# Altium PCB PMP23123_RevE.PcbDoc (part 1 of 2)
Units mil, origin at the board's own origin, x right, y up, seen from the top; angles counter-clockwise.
Board outline 4000 x 3800 mil, 4 copper layers (Top Layer, Layer 1, Layer 2, Bottom Layer), stack 76 mil thick; 128 components, 55 nets, 360 pads, 207 vias.
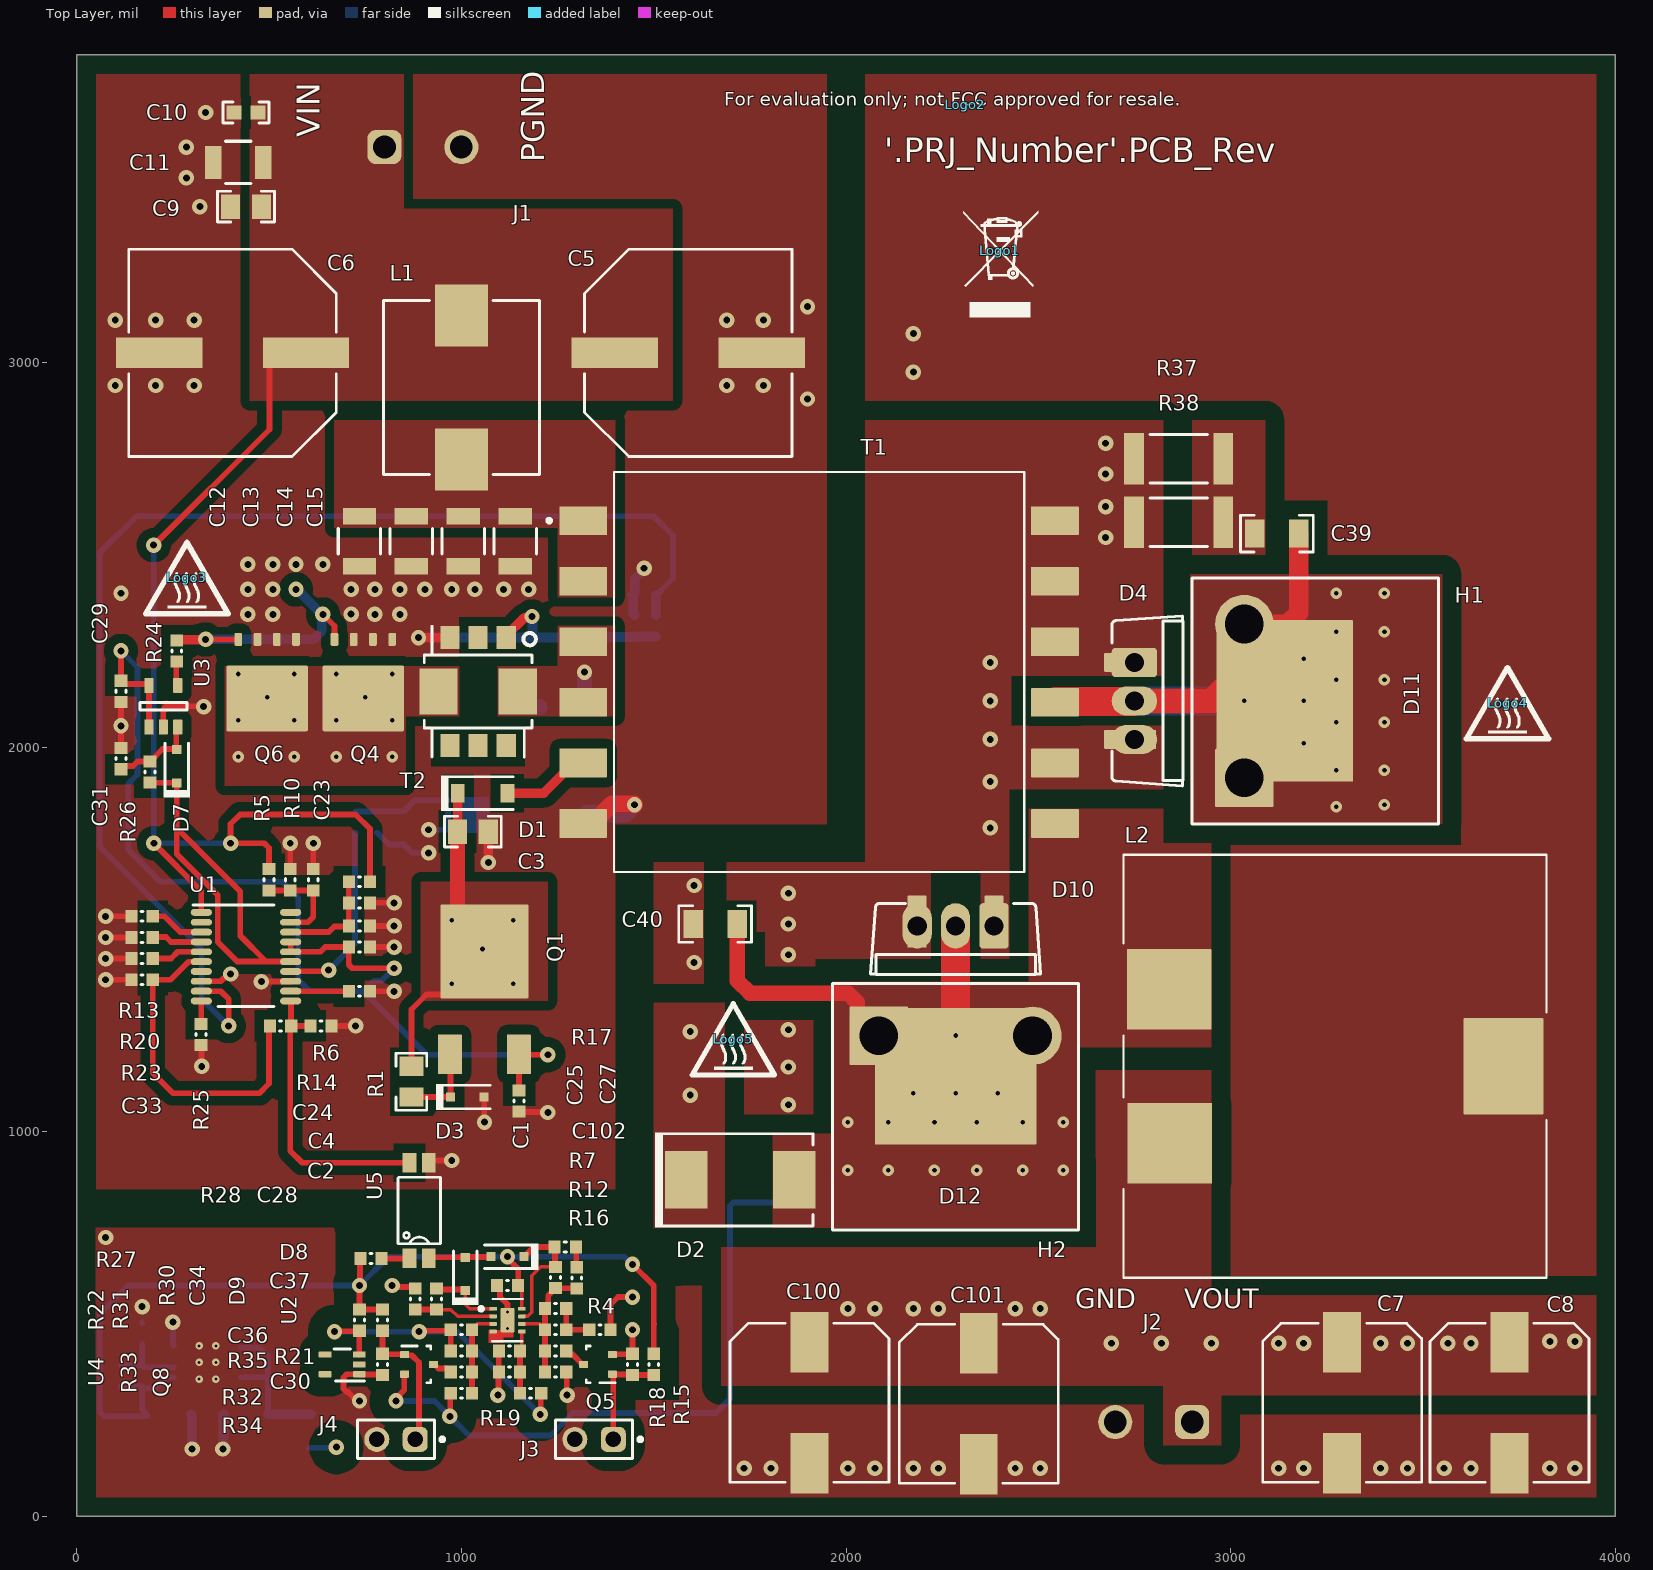
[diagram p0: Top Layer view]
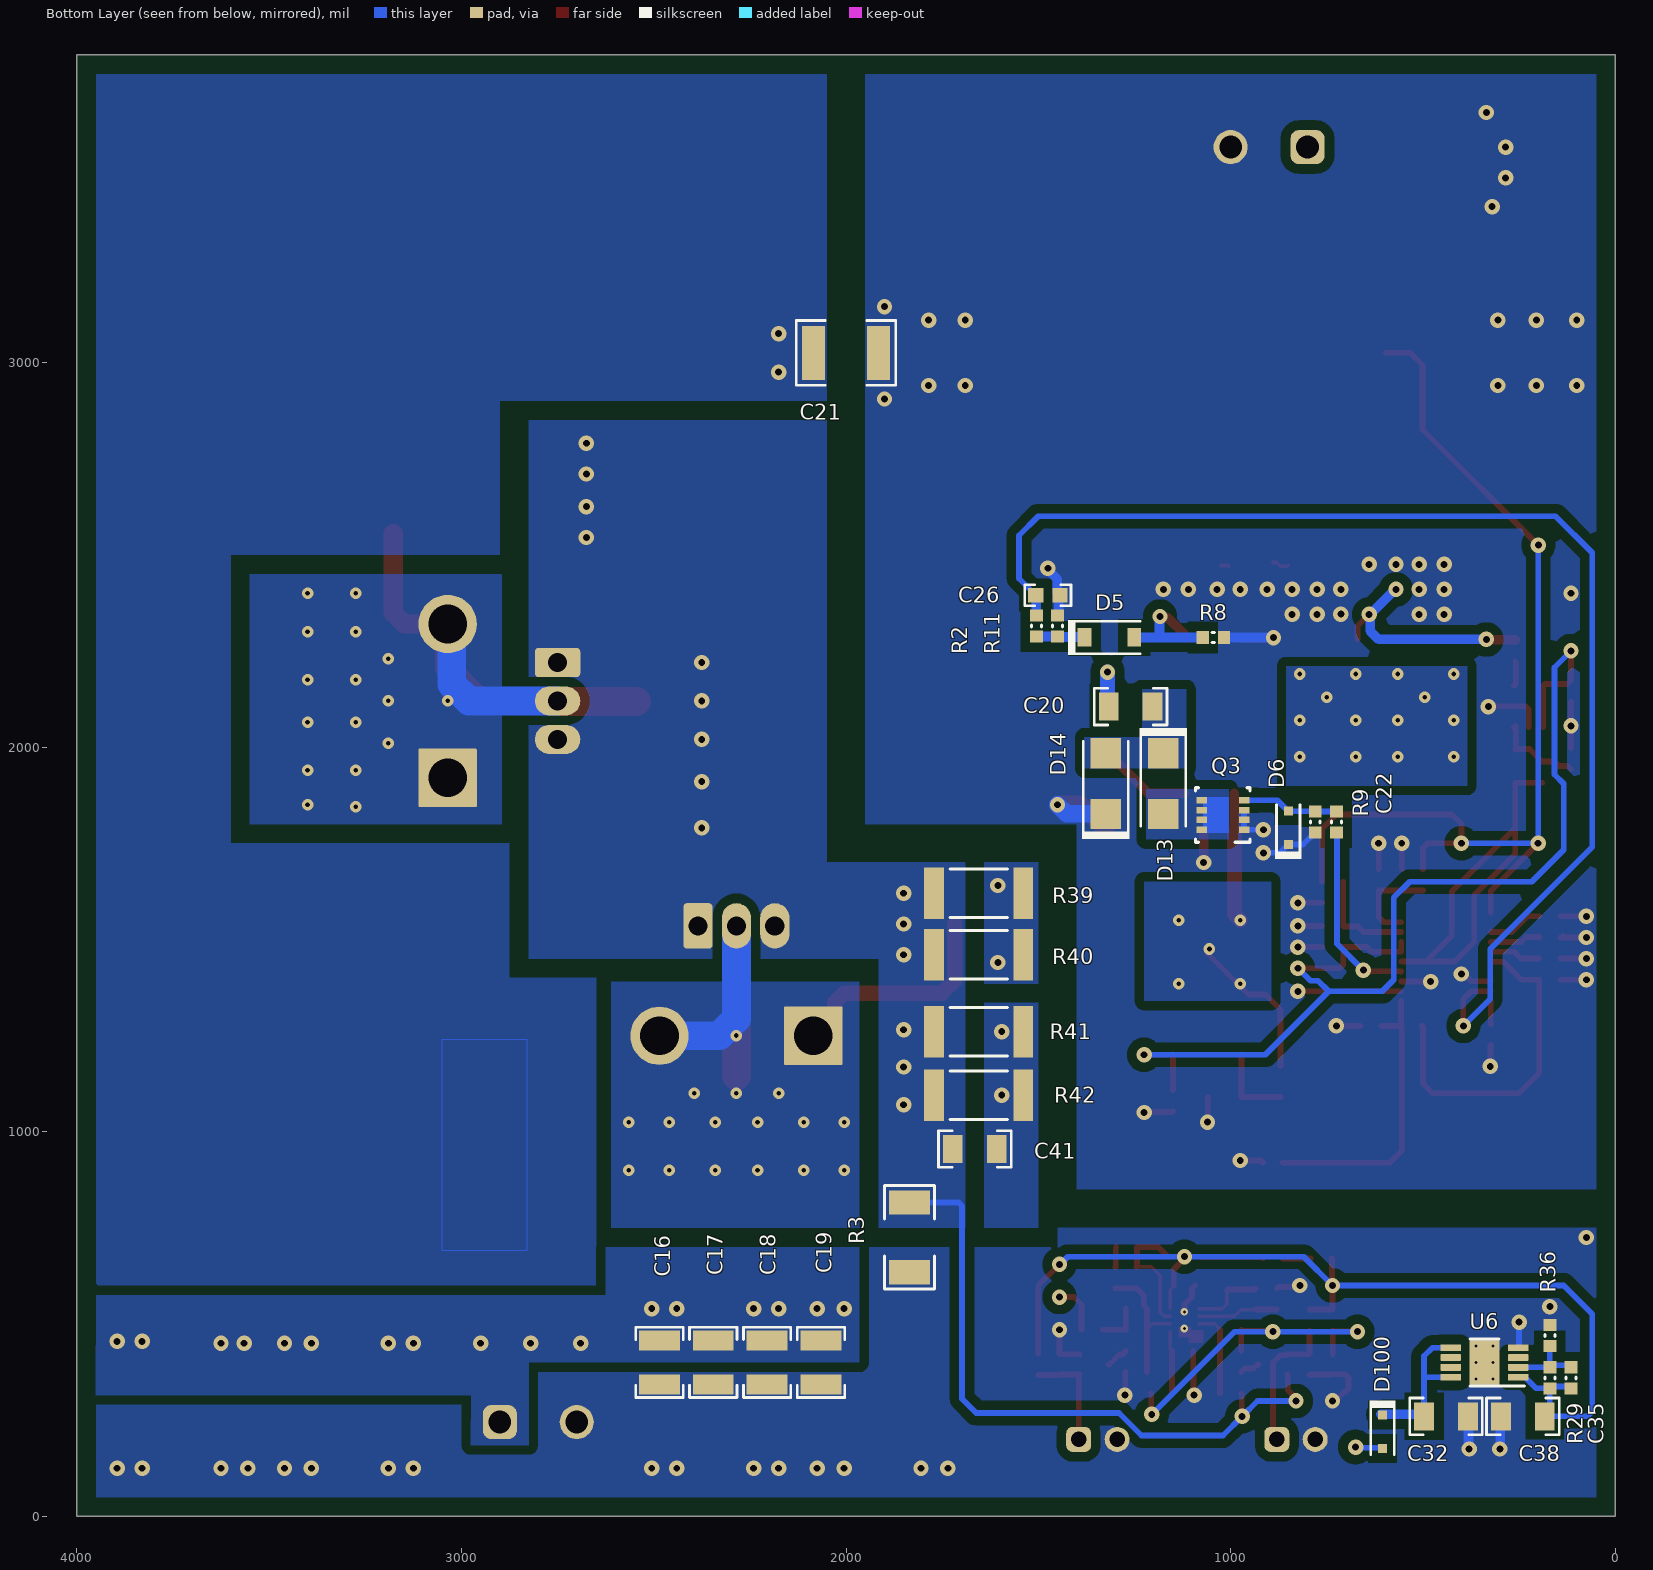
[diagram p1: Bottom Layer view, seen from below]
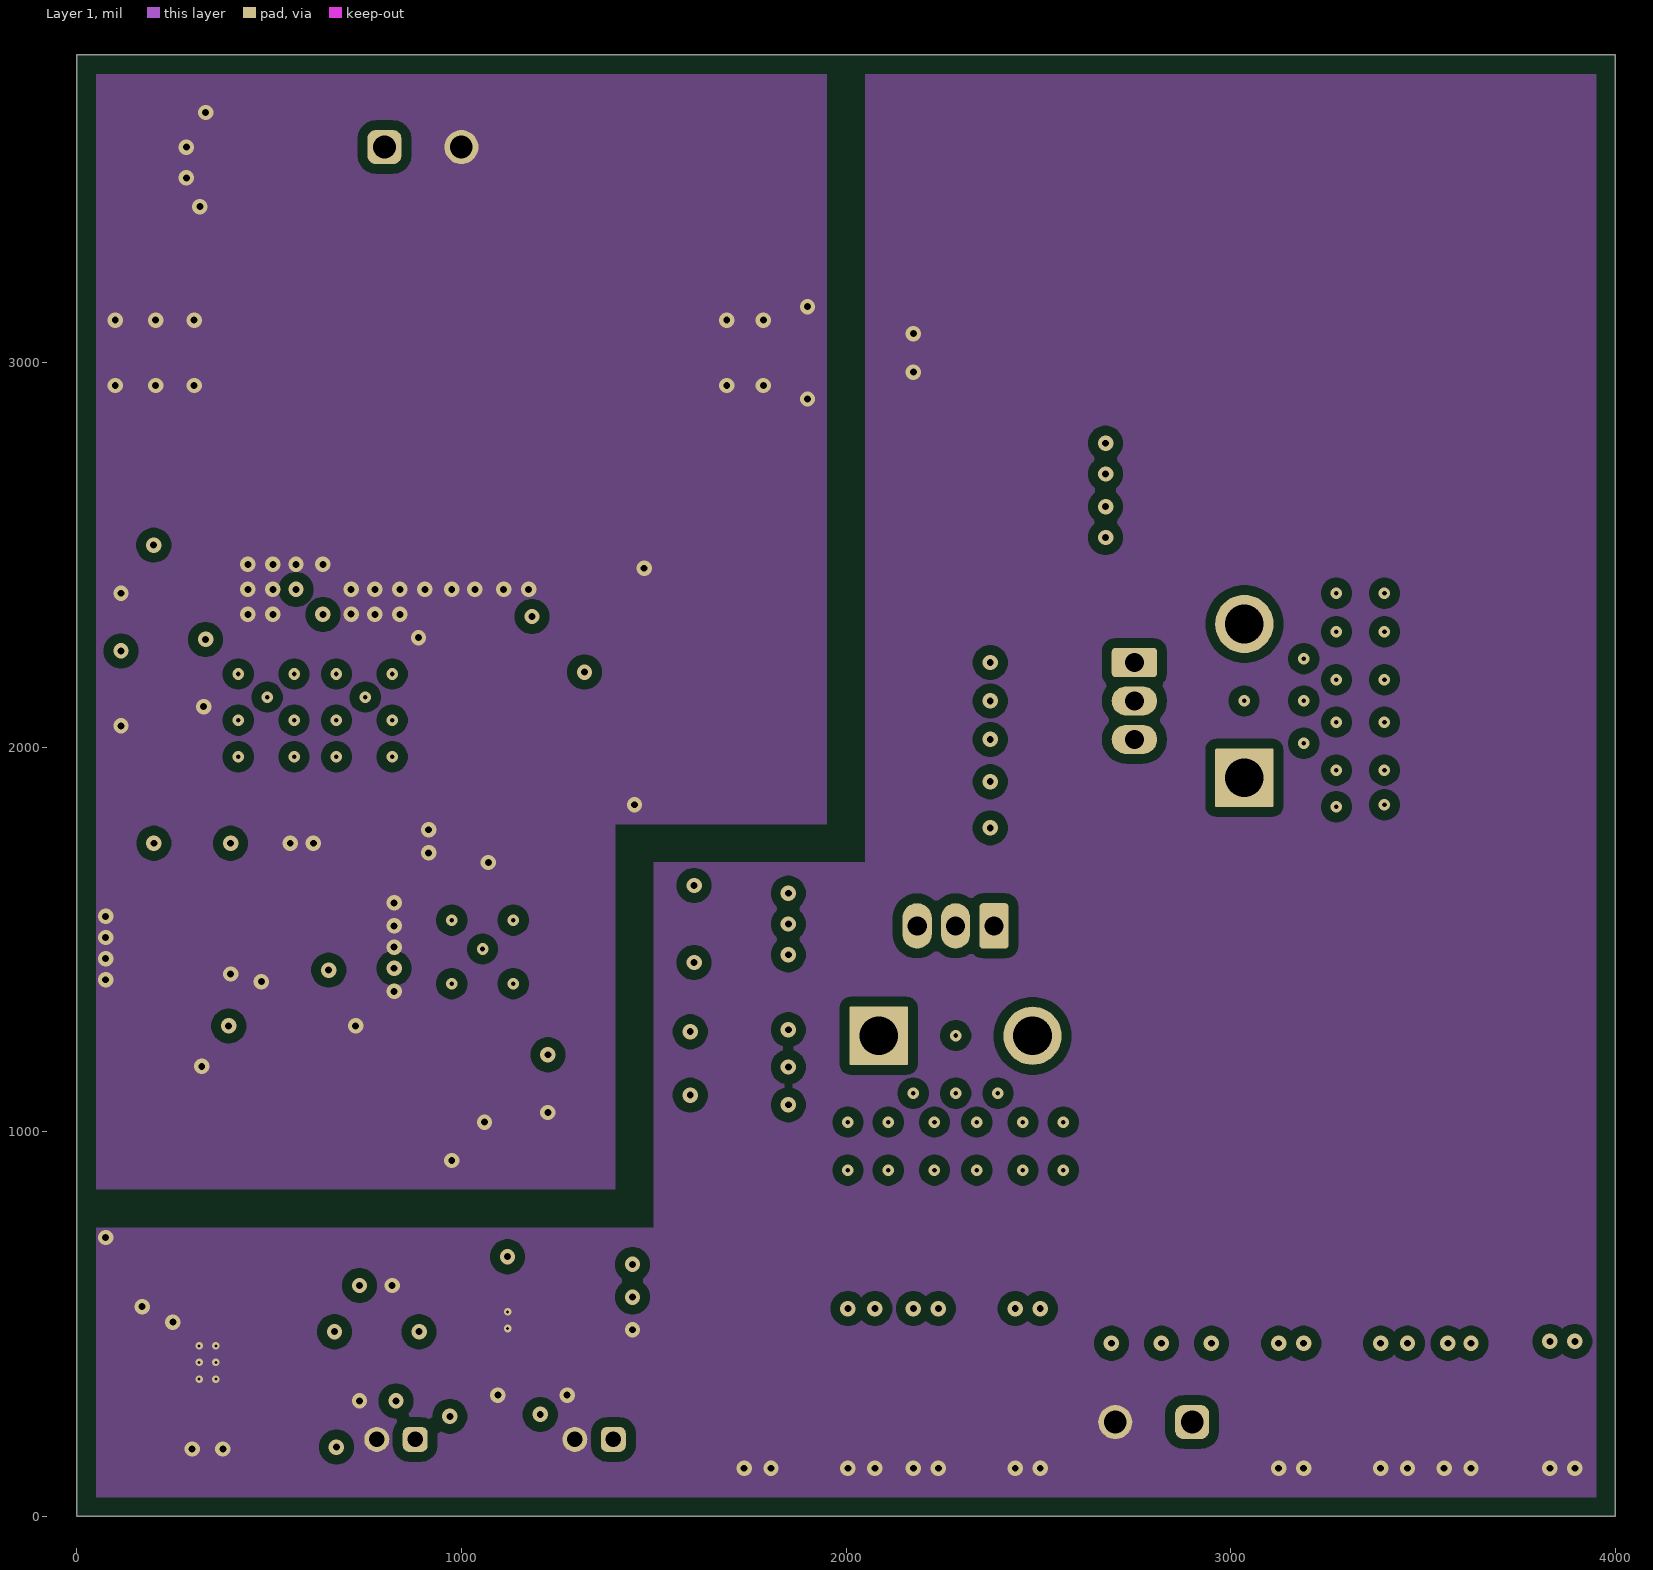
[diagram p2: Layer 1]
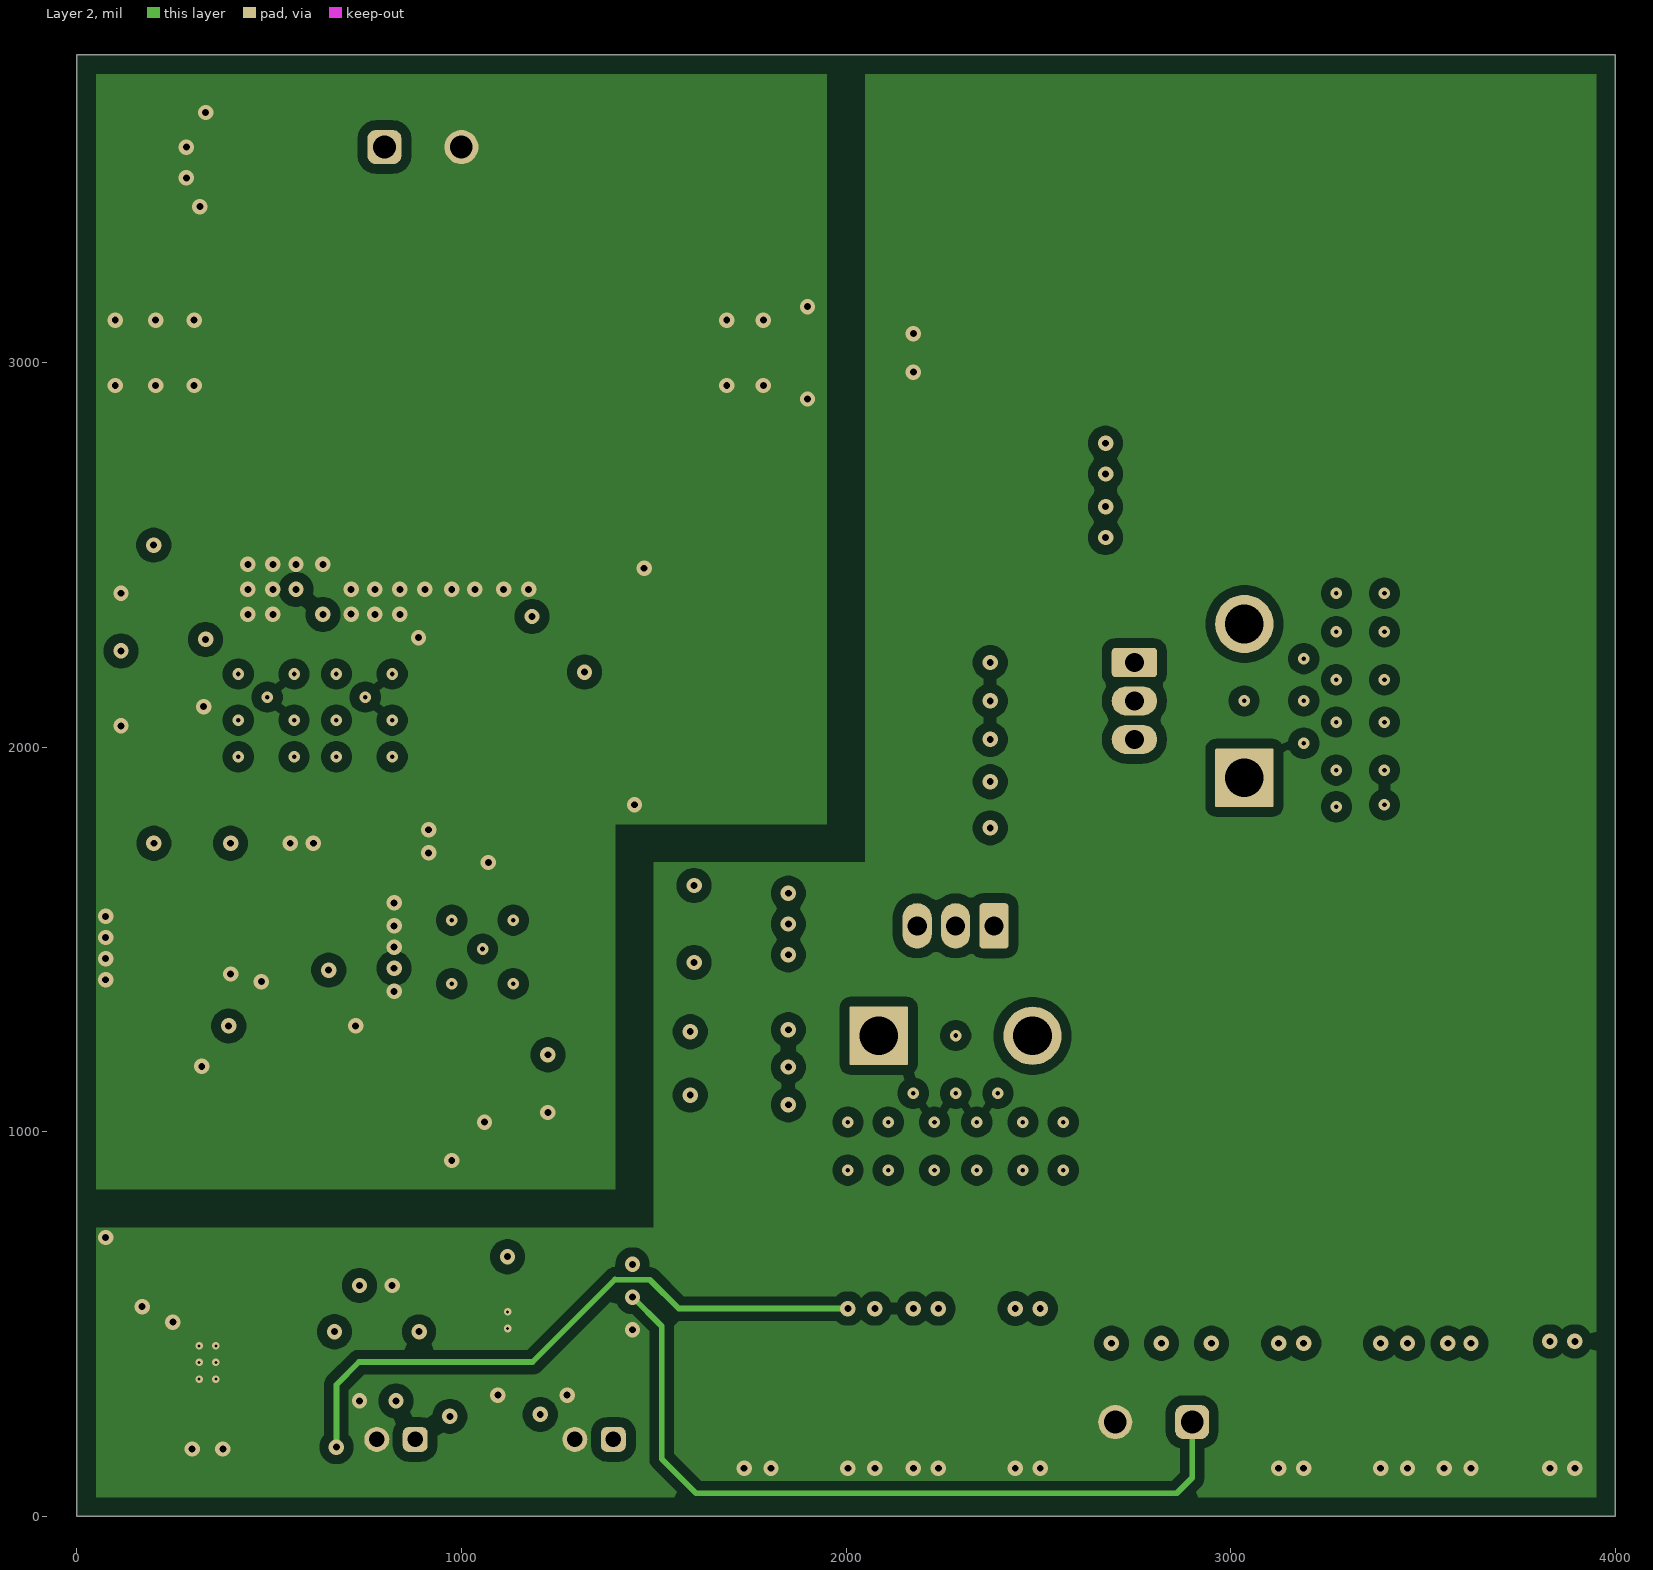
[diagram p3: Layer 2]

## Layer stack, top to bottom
Top Solder: solder mask 0.4, Solder Resist, Dk 3.5
Top Layer: signal copper 2.8
Dielectric 1: prepreg 2.8, PP-006, Dk 4.1
Layer 1: signal copper 2.8
Dielectric1: core 59.2, FR-4 High Tg, Dk 4.8
Layer 2: signal copper 2.8
Dielectric 2: prepreg 2.8, PP-006, Dk 4.1
Bottom Layer: signal copper 2.8
Bottom Solder: solder mask 0.4, Solder Resist, Dk 3.5

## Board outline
0,0 0,3800 4000,3800 4000,0

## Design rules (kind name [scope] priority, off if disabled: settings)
AcuteAngle [All] p1: minimum=4.50000000000000E+0001 checktracksonly=FALSE
AssemblyTestPointUsage [All] p1: valid=2
BoardOutlineClearance BoardOutlineClearance_MountingHoles [OnCopper and InComponentClass('Mounting Holes')] p1: gap=39.37 ignorepadtopadclearanceinfootprint=FALSE
BoardOutlineClearance BoardOutlineClearance_Poly [OnCopper and IsPoly] p2: gap=25 ignorepadtopadclearanceinfootprint=FALSE
BoardOutlineClearance [OnCopper and Not InComponentClass('Logo') and not InComponentClass('FiducialMark') and not InRegion(1000,500,4000,800) and not InPoly] p3: gap=40 ignorepadtopadclearanceinfootprint=FALSE
Clearance Clearance_1 [InNamedPolygon('TOP_LAYER_GND_P051')] p1: gap=50 ignorepadtopadclearanceinfootprint=FALSE
Clearance Clearance_Keepouts [((IsTrack Or IsArc) And Not InPoly) And IsFree and IsKeepOut vs ((IsTrack Or IsArc) And Not InPoly) And IsFree and IsKeepOut] p2: gap=0 ignorepadtopadclearanceinfootprint=FALSE
Clearance Clearance_Poly [InPolygon] p3: gap=25 ignorepadtopadclearanceinfootprint=TRUE
Clearance Clearance_FiducialMark [IsKeepOut and InComponentClass('FiducialMark') vs IsPad and InComponentClass('FiducialMark')] p4: gap=0 ignorepadtopadclearanceinfootprint=FALSE
Clearance [All] p5: gap=7.87 ignorepadtopadclearanceinfootprint=TRUE
ComponentClearance ComponentClearance_4 [InComponent('D12') vs InComponent('H2')] p1: gap=0 collisioncheckmode=3 verticalgap=0 showdistances=FALSE
ComponentClearance ComponentClearance_3 [InComponent('D12') vs InComponent('D10')] p2: gap=0 collisioncheckmode=3 verticalgap=0 showdistances=FALSE
ComponentClearance ComponentClearance_2 [InComponent('D11') vs InComponent('H1')] p3: gap=0 collisioncheckmode=3 verticalgap=0 showdistances=FALSE
ComponentClearance ComponentClearance_1 [InComponent('D11') vs InComponent('D4')] p4: gap=0 collisioncheckmode=3 verticalgap=0 showdistances=FALSE
ComponentClearance ComponentClearance_MountingHoles_FiducialMarks [InComponentClass('Mounting Holes') vs InComponentClass('FiducialMark')] p5: gap=50 collisioncheckmode=3 verticalgap=10 showdistances=FALSE
ComponentClearance ComponentClearance_Shunt [InComponentClass('Header') vs InComponentClass('Shunt')] p6: gap=0 collisioncheckmode=3 verticalgap=0 showdistances=FALSE
ComponentClearance ComponentClearance_Logo [InComponentClass('Logo')] p7: gap=30 collisioncheckmode=3 verticalgap=10 showdistances=FALSE
ComponentClearance ComponentClearance_ScrewToNut [(HasFootprint('NY PMS 440 0025 PH')) vs (HasFootprint('Keystone_1902C'))] p8: gap=5 collisioncheckmode=3 verticalgap=10 showdistances=FALSE
ComponentClearance ComponentClearance_MountingHoles [InComponentClass('Mounting Holes')] p9: gap=100 collisioncheckmode=3 verticalgap=100000 showdistances=FALSE
ComponentClearance ComponentClearance_SmallPassives [HasFootprint('0201*') or HasFootprint('0402*') or HasFootprint('0508') or HasFootprint('0603*') or HasFootprint('0612') or HasFootprint('0805*') or HasFootprint('0815*') or HasFootprint('0830*') or HasFootprint('1206*') or HasFootprint('1210*') or HasFootprint('1808*') or HasFootprint('1812*') or HasFootprint('1825*') or HasFootprint('2010*') or HasFootprint('2220*') or HasFootprint('2225*') or HasFootprint('2512*') or HasFootprint('2728*') or HasFootprint('3518*') vs HasFootprint('0201*') or HasFootprint('0402*') or HasFootprint('0508') or HasFootprint('0603*') or HasFootprint('0612') or HasFootprint('0805*') or HasFootprint('0815*') or HasFootprint('0830*') or HasFootprint('1206*') or HasFootprint('1210*') or HasFootprint('1808*') or HasFootprint('1812*') or HasFootprint('1825*') or HasFootprint('2010*') or HasFootprint('2220*') or HasFootprint('2225*') or HasFootprint('2512*') or HasFootprint('2728*') or HasFootprint('3518*')] p10: gap=14.96 collisioncheckmode=3 verticalgap=10 showdistances=FALSE
ComponentClearance ComponentClearance_THtoSMT [IsThruComponent vs IsSMTComponent] p11: gap=30 collisioncheckmode=3 verticalgap=30 showdistances=FALSE
ComponentClearance ComponentClearance_THtoTH [IsThruComponent vs IsThruComponent] p12: gap=20 collisioncheckmode=3 verticalgap=30 showdistances=FALSE
ComponentClearance [All] p13: gap=20 collisioncheckmode=3 verticalgap=10 showdistances=FALSE
DiffPairsRouting [All] p1: maxlimit=100 minlimit=10 mostfreqgap=10 toplayer_minwidth=15 toplayer_maxwidth=15 toplayer_prefwidth=15 midlayer1_minwidth=15 midlayer1_maxwidth=15 midlayer1_prefwidth=15 midlayer2_minwidth=15 midlayer2_maxwidth=15 midlayer2_prefwidth=15 bottomlayer_minwidth=15 bottomlayer_maxwidth=15 bottomlayer_prefwidth=15 maxuncoupledlength=1000
FabricationTestPointUsage TestPointUsage [All] p1: valid=2 allowmultiple=FALSE
FabricationTestpoint Testpoint [All] p1: side=3 testpointundercomponent=TRUE minsize=40 maxsize=100 preferedsize=60 minholesize=0 maxholesize=40 preferedholesize=32 testpointgrid=1 allowsidetop=TRUE allowsidebottom=TRUE usegrid=TRUE gridtolerance=0.01
FanoutControl Fanout_LCC [IsLCC] p1: bgadir=Out bgaviamode=Centered fanoutstyle=Auto fanoutdirection=Alternating viagrid=1 // Fanout_LCC (Default Rule)
FanoutControl Fanout_BGA [IsBGA] p2: bgadir=Out bgaviamode=Centered fanoutstyle=Auto fanoutdirection=Alternating viagrid=1 // Fanout_BGA (Default Rule)
FanoutControl Fanout_Default [All] p4: bgadir=Out bgaviamode=Centered fanoutstyle=Auto fanoutdirection=Alternating viagrid=1 // Fanout_Default (Default Rule)
FanoutControl Fanout_Small [(CompPinCount < 5)] p5: bgadir=Out bgaviamode=Centered fanoutstyle=Auto fanoutdirection=OutThenIn viagrid=1 // Fanout_Small (Default Rule)
HoleSize [All] p1: absolutevalues=TRUE maxlimit=251 minlimit=7.87 maxpercent=80.000 minpercent=20.000
MinimumAnnularRing MinimumAnnularRing_ThermalPadVias [IsVia and InAnyComponent] p1: minimumring=5.91
MinimumAnnularRing [All] p2: minimumring=7.87
MinimumSolderMaskSliver MinimumSolderMaskSliver_Logo [InComponentClass('Logo') vs InComponentClass('Logo')] p1: minsoldermaskwidth=0.7
MinimumSolderMaskSliver [All] p2: minsoldermaskwidth=3.94
PlaneConnect [All] p1: planeconnectstyle=Relief reliefexpansion=10 reliefentries=4 reliefconductorwidth=10 reliefairgap=10
PolygonConnect [All] p1: connectstyle=Direct reliefconductorwidth=10 reliefentries=4 polygonreliefangle="90 Angle" airgapwidth=10
RoutingVias ThermalPadVias [IsVia and InAnyComponent] p1: holewidth=7.87 width=19.68 viastyle="Through Hole" minholewidth=7.87 minwidth=19.68 maxholewidth=12.99 maxwidth=23.62
RoutingVias [All] p2: holewidth=18 width=40 viastyle="Through Hole" minholewidth=7.87 minwidth=24 maxholewidth=40 maxwidth=65
SilkToBoardRegionClearance [Not ((IsComment or IsDesignator) And (Hide <> 'False')) and not InRegion(1000,500,4000,800)] p1:
SilkToSilkClearance SilkToSilkClearance_Pb-FreeLogo [(HasFootprint('Pb-Free_Overlay_Medium') OR HasFootprint('Pb-Free_Overlay_Small')) vs (HasFootprint('Pb-Free_Overlay_Medium') OR HasFootprint('Pb-Free_Overlay_Small'))] p1: silktosilkclearance=0
SilkToSilkClearance [All] p2: silktosilkclearance=3.94
SilkToSolderMaskClearance SilkToComponentPadClearance [(IsPad or IsFill or IsRegion) and InAnycomponent] p1: minsilkscreentomaskgap=5 clearancetoexposedcopper=TRUE
SilkToSolderMaskClearance "Silk to Solder Mask Opening" [All] p2: minsilkscreentomaskgap=3.94 clearancetoexposedcopper=FALSE
SolderMaskExpansion [All] p1: expansion=1.97 istentingtop=FALSE
UnRoutedNet [All] p1: checkbadconnections=TRUE
Width [All] p1: maxlimit=100 minlimit=6 preferedwidth=10 checkconnectedcopper=TRUE
14 further rules are at their usual default settings.

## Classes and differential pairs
component class PMP23123_RevE_SH2: C32 C35 C38 C39 C40 C41 D2 D4 D10 D11 D12 D100 H1 H2 Logo4 Logo5 R29 R36 R37 R38 R39 R40 R41 R42 U6
component class PMP23123_RevE_SH1: C1 C2 C3 C4 C5 C6 C7 C8 C9 C10 C11 C12 C13 C14 C15 C16 C17 C18 C19 C20 C21 C22 C23 C24 C25 C26 C27 C28 C29 C30 C31 C33 C34 C36 C37 C100 C101 C102 D1 D3 D5 D6 D7 D8 D9 D13 D14 J1 J2 J3 J4 L1 L2 Logo1 Logo2 Logo3 Q1 Q3 Q4 Q5 Q6 Q8 R1 R2 R3 R4 R5 R6 R7 R8 R9 R10 R11 R12 R13 R14 R15 R16 R17 R18 R19 R20 R21 R22 R23 R24 R25 R26 R27 R28 R30 R31 R32 R33 R34 R35 T1 T2 U1 U2 U3 U4 U5
component class Header: J3 J4

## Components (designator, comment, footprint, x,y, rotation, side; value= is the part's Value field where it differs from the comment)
C1 "C0603C105K3RACTU" 0603L 1150,1080 r90 top value=1uF
C2 "GRM188R71E473KA01D" 0603L 735,1365 r0 top value=0.047uF
C3 "C0805C105K5RACTU" 0805_HV 1030,1780 r180 top value=1uF
C4 "C0603C105K3RACTU" 0603L 735,1480 r180 top value=1uF
C5 "EEV-FK1H331Q" SM_RADIAL_H13 1590,3025 r0 top value=330uF
C6 "EEV-FK1H331Q" SM_RADIAL_H13 405,3025 r180 top value=330uF
C7 "HHXD630ARA820MJA0G" SM_RADIAL_10BMM 3290,295 r270 top value=82uF
C8 "HHXD630ARA820MJA0G" SM_RADIAL_10BMM 3725,295 r270 top value=82uF
C9 "C0805C105K5RACTU" 0805_HV 440,3405 r0 top value=1uF
C10 "C0603C104K5RACTU" 0603 440,3650 r0 top value=0.1uF
C11 "UMK325AB7106KM-T" 1210_280 420,3520 r0 top value=10uF
C12 "UMK325AB7106KM-T" 1210_280 735,2535 r90 top value=10uF
C13 "UMK325AB7106KM-T" 1210_280 870,2535 r90 top value=10uF
C14 "UMK325AB7106KM-T" 1210_280 1005,2535 r90 top value=10uF
C15 "UMK325AB7106KM-T" 1210_280 1140,2535 r90 top value=10uF
C16 "C1210C225K1RACTU" 1210_210 2485,400 r90 bottom value=2.2uF
C17 "C1210C225K1RACTU" 1210_210 2345,400 r90 bottom value=2.2uF
C18 "C1210C225K1RACTU" 1210_210 2205,400 r90 bottom value=2.2uF
C19 "C1210C225K1RACTU" 1210_210 2065,400 r90 bottom value=2.2uF
C20 "GRM31MR72A154KA01L" 1206 1260,2105 r180 bottom value=0.15uF
C21 "C4532X7R3D222K130KA" 1812_HV 2000,3025 r180 bottom value=2200pF
C22 "885012206071" 0603L 725,1805 r270 bottom value=0.1uF
C23 "885012206083" 0603L 615,1655 r270 top value=1000pF
C24 "885012206083" 0603L 735,1535 r180 top value=1000pF
C25 "C0603C100J5GACTU" 0603L 1245,620.67 r90 top value=10pF
C26 "885012006057" 0603 1475,2395 r0 bottom value=100pF
C27 "885012206070" 0603L 1300,620 r90 top value=0.068uF
C28 "885012206083" 0603L 635,1275 r180 top value=1000pF
C29 "C0603C105K3RACTU" 0603L 115,2145 r270 top value=1uF
C30 "C0603C103K5RACTU" 0603L 1125,375 r180 top value=0.01uF
C31 "C0603C470J5GACTU" 0603L 115,1970 r90 top value=47pF
C32 "885012208041" 1206 440,260 r0 bottom value=10uF
C33 "885012206071" 0603L 170,1395 r0 top value=0.1uF
C34 "C0603C103K5RACTU" 0603L 935,565 r90 top value=0.01uF
C35 "C0603C103K5RACTU" 0603L 115,360 r90 bottom value=0.01uF
C36 "C0603C103K5RACTU" 0603L 1000,485 r180 top value=0.01uF
C37 "C0603C103K5RACTU" 0603L 1120,600 r0 top value=0.01uF
C38 "885012208041" 1206 240,260 r180 bottom value=10uF
C39 "VJ1206Y221KXEAT5Z" 1206 3120,2555 r0 top value=220pF
C40 "VJ1206Y221KXEAT5Z" 1206 1660,1540 r0 top value=220pF
C41 "VJ1206Y103KXEAT5Z" 1206 1665,955 r180 bottom value=0.01uF
C100 "HHXD630ARA820MJA0G" SM_RADIAL_10BMM 1905,295 r270 top value=82uF
C101 "HHXD630ARA820MJA0G" SM_RADIAL_10BMM 2345,292.48 r270 top value=82uF
C102 "C0603C181J5GACTU" 0603L 1245,540 r0 top value=180pF
D1 "MMSD4148T1G" SOD-123 1055,1880 r0 top value=100V
D2 "MURS340T3G" SMC 1725,875 r0 top value=400V
D3 "MMSZ5243BS-7-F" SOD-323 1015,1090 r0 top value=13V
D4 "VS-30CTH03-M3" TO-220AB 2750,2120 r270 top value=300V
D5 "RF081M2STR" SOD-123 1315,2285 r180 bottom value=200V
D6 "MMDL914-TP" SOD-323 850,1790 r90 bottom value=100V
D7 "MMDL914-TP" SOD-323 260,1950 r90 top value=100V
D8 "MMDL914-TP" SOD-323 1120,675 r180 top value=100V
D9 "MMDL914-TP" SOD-323 1010,630 r90 top value=100V
D10 "VS-30CTH03-M3" TO-220AB 2285,1535 r180 top value=300V
D11 "STTH30R03CG" DDPAK 2985,2120 r0 top value=300V
D12 "STTH30R03CG" DDPAK 2285,1300 r270 top value=300V
D13 "B1100-13-F" SMA 1175,1905 r270 bottom value=100V
D14 "ES1B-13-F" SMA 1325,1905 r90 bottom value=100V
D100 "MMDL914-TP" SOD-323 605,220 r270 bottom value=100V
H1 "634-20ABP" FP-634-20ABP_PTH_16MM26_16MM26-MFG 3220,2120 r90 top
H2 "634-20ABP" FP-634-20ABP_PTH_16MM26_16MM26-MFG 2285,1065 r0 top
J1 "691236510002" Wurth_691236510002 900,3560 r0 top
J2 "691236510002" Wurth_691236510002 2800,245 r180 top
J3 "TSW-102-07-G-S" TSW-102-07-G-S 1345,200 r180 top
J4 "TSW-102-07-G-S" TSW-102-07-G-S 830,200 r180 top
L1 "PA4342.472NLT" PA4342_2 1000,2935 r0 top value=4.7uH
L2 "SER3018H-333KE" FP-SER3018H-333KE_SMT3_27MM94_27MM94-MFG 3271.5,1170 r270 top value=33uH
Logo1 "WEEE logo" WEEE_Minimum 2400,3290 r0 top
Logo2 "FCC disclaimer" FCC_disclaimer 2310,3670 r0 top
Logo3 "CAUTION HOT SURFACE" IEC_HotSurface_Small 286.46,2440 r0 top
Logo4 "CAUTION HOT SURFACE" IEC_HotSurface_Small 3720,2114.37 r0 top
Logo5 "CAUTION HOT SURFACE" IEC_HotSurface_Small 1707.09,1240.31 r0 top
Q1 "NJD2873T4G" DPAK 1060,1335 r90 top value="50 V"
Q3 "FDMC2523P" MLP08S 1020.12,1823.39 r0 bottom value=-150V
Q4 "CSD19532Q5B" DNK0008A 745,2168.98 r270 top value=100V
Q5 "2N7002W-7-F" SOT-323 1355,395 r180 top value=60V
Q6 "CSD19532Q5B" DNK0008A 495,2168.98 r270 top value=100V
Q8 "2N7002W-7-F" SOT-323 890,395 r0 top value=60V
R1 "CRCW08055K10JNEA" 0805_HV 870,1130 r90 top value=5.1k
R2 "CRCW06031K50FKEA" 0603L 1505,2315 r90 bottom value=1.50k
R3 "WSL20105L000FEA" 2010 1835,725 r270 bottom value=0.005
R4 "CRCW06030000Z0EA" 0603L 1360,485 r0 top value=0
R5 "CRCW060360K4FKEA" 0603L 500,1655 r90 top value=60.4k
R6 "CRCW060360K4FKEA" 0603L 735,1650 r0 top value=60.4k
R7 "CRCW060330K1FKEA" 0603L 1245,485 r180 top value=30.1k
R8 "CRCW06034K99FKEA" 0603L 1045,2285 r0 bottom value=4.99k
R9 "CRCW060310K0FKEA" 0603L 780,1805 r270 bottom value=10.0k
R10 "CRCW06032K00FKEA" 0603L 555,1655 r90 top value=2.00k
R11 "CRCW06031R50FKEA" 0603L 1450,2315 r90 bottom value=1.50
R12 "CRCW06037K15FKEA" 0603L 1245,430 r0 top value=7.15k
R13 "CRCW060315K0FKEA" 0603L 170,1560 r180 top value=15.0k
R14 "CRCW06035K23FKEA" 0603L 735,1595 r0 top value=5.23k
R15 "CRCW060310K0FKEA" 0603L 1500,395 r270 top value=10.0k
R16 "CRCW060310K7FKEA" 0603L 1245,375 r0 top value=10.7k
R17 "CRCW0603130KFKEA" 0603L 1270,700 r0 top value=130k
R18 "CRCW060310K0FKEA" 0603L 1445,395 r90 top value=10.0k
R19 "CRCW0603100KFKEA" 0603L 1180,320 r0 top value=100k
R20 "CRCW0603110KFKEA" 0603L 170,1505 r0 top value=110k
R21 "CRCW0603402KFKEA" 0603L 1125,430 r180 top value=402k
R22 "CRCW06032K00FKEA" 0603L 735,510 r270 top value=2.00k
R23 "CRCW060364K9FKEA" 0603L 170,1450 r0 top value=64.9k
R24 "CRCW06032R20JNEA" 0603L 260,2250 r270 top value=2.2
R25 "CRCW060364K9FKEA" 0603L 323.34,1252.76 r90 top value=64.9k
R26 "CRCW06030000Z0EA" 0603L 190,1935 r90 top value=0
R27 "CRCW06031K50FKEA" 0603L 765,670 r0 top value=1.50k
R28 "CRCW06031K50FKEA" 0603L 530,1275 r180 top value=1.50k
R29 "CRCW0603100KFKEA" 0603L 170,360 r270 bottom value=100k
R30 "CRCW0603604RFKEA" 0603L 880,565 r90 top value=604
R31 "CRCW060310K0FKEA" 0603L 795,510 r270 top value=10.0k
R32 "CRCW06031K13FKEA" 0603L 1000,375 r0 top value=1.13k
R33 "CRCW060310K0FKEA" 0603L 795,395 r270 top value=10.0k
R34 "CRCW0603732RFKEA" 0603L 1000,320 r180 top value=732
R35 "CRCW0603110KFKEA" 0603L 1000,430 r0 top value=110k
R36 "CRCW060318K7FKEA" 0603L 170,470 r90 bottom value=18.7k
R37 "CRCW2512150RJNEG" 2512 2865,2750 r180 top value=150
R38 "CRCW2512150RJNEG" 2512 2865,2585 r180 top value=150
R39 "CRCW2512150RJNEG" 2512 1655,1620 r0 bottom value=150
R40 "CRCW2512150RJNEG" 2512 1655,1460 r0 bottom value=150
R41 "CRCW251239K0JNEG" 2512 1655,1260 r0 bottom value=39k
R42 "CRCW251239K0JNEG" 2512 1655,1095 r0 bottom value=39k
T1 "PAT6586NL" FP-PAT6586NL_SMT_XFRMR_27MM1_26MM42-MFG 1930,2195 r0 top
T2 "PA1005.100NL" P82xx 1043.5,2144.45 r270 top
U1 "UCC2897APWR" PW0020A_N 440,1455 r0 top
U2 "OPA2170AIDSGR" DSG0008A-MFG 1120,510 r0 top
U3 "UCC27519DBVR" DBV0005A_N 225.07,2106.22 r90 top
U4 "LM4040D50IDCKR" DCK0005A_N 690,395 r180 top
U5 "TCMT1107" SOP-4 890,795 r90 top
U6 "TPS7A1601DGNR" DGN0008C_N 340,400 r0 bottom

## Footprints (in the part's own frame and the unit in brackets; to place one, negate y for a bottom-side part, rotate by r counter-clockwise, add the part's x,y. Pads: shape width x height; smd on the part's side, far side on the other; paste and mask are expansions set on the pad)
0603 [mm] "0603 from SM-752 data"
  rect 1x0.95 smd: 1(-0.8,0) 2(0.8,0)
  silkscreen extent -1.52,-0.69 1.52,0.69, body extent -0.87,-0.47 0.87,0.47, height 1
0603L [mm] "0603 from SM-752 data"
  rect 0.8x0.85 smd: 1(-0.7,0) 2(0.7,0)
  silkscreen extent -0.07,-0.33 0.07,0.33, body extent -0.87,-0.47 0.87,0.47, height 1
0805_HV [mil] "0805 with 30mil clearance between pads"
  rect 50x63 smd: 1(-40,0) 2(40,0)
  silkscreen extent -74,-40 74,40, body extent -43,-29 43,29, height 57
1206 [mm] "1206 from SM-752 data"
  rect 1.3x1.85 smd: 1(-1.45,0) 2(1.45,0)
  silkscreen extent -2.4,-1.21 2.4,1.21, body extent -1.7,-0.9 1.7,0.9, height 1.35
1210_210 [mm] "1210"
  rect 1.3x2.7 smd: 1(-1.45,0) 2(1.45,0)
  silkscreen extent -2.32,-1.57 2.32,1.57, body extent -1.7,-1.35 1.7,1.35, height 2.1
1210_280 [mm] "SMD, 2-Leads, Body 3.6x2.8mm, Height 2.8mm"
  rect 1.1x2.2 smd: 1(-1.65,0) 2(1.65,0)
  silkscreen extent -0.84,-1.4 0.84,1.4, body extent -1.8,-1.4 1.8,1.4, height 2.8
1812_HV [mil] "PRG recommended land pattern"
  rect 60x140 smd: 1(-85,0) 2(85,0)
  silkscreen extent -129,-84 129,84, body extent -94,-67 94,67, height 53
2010 [mm] "Chip Capacitor, Body 5.08x2.54mm, IPC Medium Density"
  rect 1.6x2.7 smd: 1(-2.3,0) 2(2.3,0)
  silkscreen extent -3.42,-1.65 3.42,1.65, body extent -2.73,-1.45 2.73,1.45, height 1.66
2512 [mm] "Chip Resistor, Body 6.3x3.2mm, IPC Medium Density"
  rect 1.3x3.4 smd: 1(-2.95,0) 2(2.95,0)
  silkscreen extent -1.9,-1.6 1.9,1.6, body extent -3.22,-1.67 3.22,1.67, height 0.71
DBV0005A_N [mm] "SOT23, 5-Leads, Body 2.9x1.6mm, Pitch 0.95mm, Lead Span 2.8mm, IPC Medium Density"
  rrect17% 1x0.6 smd: 1(-1.375,0.95) 2(-1.375,0) 3(-1.375,-0.95) 4(1.375,-0.95) 5(1.375,0.95)
  silkscreen extent -0.25,-1.55 0.25,1.55, body extent -1.42,-1.46 1.42,1.46, height 1.09
DCK0005A_N [mm] "SOT353, 5-Leads, Body 2x1.3mm, Pitch 0.65mm, Lead Span 2.1mm, IPC Medium Density"
  rrect25% 0.85x0.4 smd: 1(-1.125,0.65) 2(-1.125,0) 3(-1.125,-0.65) 4(1.125,-0.65) 5(1.125,0.65)
  silkscreen extent -1.48,-1.02 0.55,1.1, body extent -1.14,-1 1.14,1, height 0.95
DDPAK [mil] "D2-PAK, 3-Pads, Body 9.7x10.4mm (max), TO-263AB, using Vishay Silionix recommended pad sizes"
  rrect8% 135x49.49 smd: 1(-246.06,100) 3(-246.06,-100)
  rrect1% 355x420 smd paste-181.1: 2(155.51,0)
  body extent -295,-202 324,202, height 180
DGN0008C_N [mm] "TSOP, 8-Leads, Body 3x3mm, Pitch 0.65mm, Thermal Pad 1.98x1.88mm, IPC Medium Density"
  rrect22% 1.35x0.45 smd: 1(-2.225,0.975) 2(-2.225,0.325) 3(-2.225,-0.325) 4(-2.225,-0.975) 5(2.225,-0.975) 6(2.225,-0.325) 7(2.225,0.325) 8(2.225,0.975)
  rrect10% 2x3 smd paste-2 mask-2: 9(0,0)
  rrect6% 1.6x1.92 on Bottom Solder: 9(0,0)
  rrect6% 1.6x1.92 on Bottom Paste: 9(0,0)
  silkscreen extent -2.65,-1.55 0.95,1.55, body extent -2.45,-1.5 2.45,1.5, height 1.1
DNK0008A [mm] "SON, 8-Leads, Body 5x6mm"
  rrect39% 0.86x0.51 smd paste-0.05 mask-0.05: 1(-2.82,1.905) 2(-2.82,0.635) 3(-2.82,-0.635) 4(-2.82,-1.905) 5(2.82,-1.905) 6(2.82,-0.635) 7(2.82,0.635) 8(2.82,1.905)
  rrect40% 0.25x0.555 on Top Solder: 9(-0.83,2.372) 9(-0.83,-2.372)
  rrect40% 0.25x0.555 on Top Paste: 9(-0.83,2.372) 9(-0.83,-2.372)
  rrect11% 0.95x1.13 on Top Paste: 9(-0.535,1.33) 9(-0.535,0) 9(-0.535,-1.33) 9(0.615,1.33) 9(0.615,0) 9(0.615,-1.33) 9(1.765,1.33) 9(1.765,0) 9(1.765,-1.33)
  rrect3% 3.58x4 on Top Solder: 9(0.75,0)
  rrect5% 4.34x5.4 smd paste-3 mask-3: 9(1.08,0)
  body extent -3.05,-2.55 3.05,2.55, height 1.06
DPAK [mm] "D-PAK, 3-Pads, Body 6.22x6.73mm (max), TO-252AA using nominal STEP model"
  rrect6% 2.6x1.6 smd: 1(-3.4,2.28) 3(-3.4,-2.28)
  rrect2% 6.2x5.8 smd paste-3: 2(3.4,0)
  body extent -3.86,-3.29 5.84,3.29, height 2.48
DSG0008A-MFG [mm]
  rrect40% 0.5x0.25 smd paste+0 mask+0: 1(-0.95,0.75) 2(-0.95,0.25) 3(-0.95,-0.25) 4(-0.95,-0.75) 5(0.95,-0.75) 6(0.95,-0.25) 7(0.95,0.25) 8(0.95,0.75)
  rrect11% 0.9x1.6 smd paste-1000 mask+0: 9(0,0)
  silkscreen extent -1.87,-1.39 1,1.4, body extent -1.3,-1.15 1.3,1.15, height 0.25
FCC_disclaimer [mil]
FP-634-20ABP_PTH_16MM26_16MM26-MFG [mm]
  rrect3% 3.85x3.85 hole 2.55 paste-1000 mask+0: 1(-5.08,4.68)
  round 3.85 hole 2.55 paste-1000 mask+0: 2(5.08,4.68)
  silkscreen extent -8.13,-8.13 8.13,8.13, body extent -8.23,-8.23 8.23,8.23, height 0.25
FP-PAT6586NL_SMT_XFRMR_27MM1_26MM42-MFG [mm]
  rrect5% 3.15x1.9 smd paste+0 mask+0: 1(-15.575,10) 2(-15.575,6) 3(-15.575,2) 4(-15.575,-2) 5(-15.575,-6) 6(-15.575,-10) 7(15.575,-10) 8(15.575,-6) 9(15.575,-2) 10(15.575,2) 11(15.575,6) 12(15.575,10)
  silkscreen extent -17.95,-13.21 13.55,13.21, body extent -17.25,-13.31 17.25,13.31, height 0.25
FP-SER3018H-333KE_SMT3_27MM94_27MM94-MFG [mm]
  rrect2% 6.35x5.28 smd paste+0 mask+0: 1(0,11.115)
  rrect2% 5.33x5.59 smd paste+0 mask+0: 2(-5.08,-10.96) 3(5.08,-10.91)
  silkscreen extent -13.97,-13.97 13.97,13.97, body extent -14.07,-14.07 14.07,14.07, height 0.25
IEC_HotSurface_Small [mil]
  silkscreen extent -107,-93 107,92
MLP08S [mm] "Fairchild MLP08S recommended land pattern"
  rect 0.7x0.42 smd mask+0.051: 1(-1.4,0.975) 2(-1.4,0.325) 3(-1.4,-0.325) 4(-1.4,-0.975) 5(1.4,-0.975) 6(1.4,-0.325) 7(1.4,0.325) 8(1.4,0.975)
  Top Layer region: -0.4,1.185 1.3,1.185 1.3,-1.185 -0.4,-1.185
  silkscreen extent -1.8,-1.8 1.8,1.8, body extent -1.67,-1.67 1.67,1.67, height 0.81
P82xx [mil] "Pulse recommended land pattern"
  rect 60x50 smd: 1(-140,73) 2(-140,0) 3(-140,-73) 4(140,-73) 5(140,0) 6(140,73)
  rect 120x100 smd: 7(0,-103) 8(0,103)
  silkscreen extent -170,-140 170,150, body extent -95,-140 95,140, height 215
PA4342_2 [mm] "SMD, 2-Leads, Body 11.5x10.3mm"
  rect 3.5x4.1 smd: 1(0,4.75) 2(0,-4.75)
  silkscreen extent -5.15,-5.75 5.15,5.75, body extent -5.15,-5.75 5.15,5.75, height 4
PW0020A_N [mm] "TSOP, 20-Leads, Body 6.5x4.4mm, Pitch 0.65mm, IPC Medium Density"
  oval 1.4x0.45 smd: 1(-2.95,2.925) 2(-2.95,2.275) 3(-2.95,1.625) 4(-2.95,0.975) 5(-2.95,0.325) 6(-2.95,-0.325) 7(-2.95,-0.975) 8(-2.95,-1.625) 9(-2.95,-2.275) 10(-2.95,-2.925) 11(2.95,-2.925) 12(2.95,-2.275) 13(2.95,-1.625) 14(2.95,-0.975) 15(2.95,-0.325) 16(2.95,0.325) 17(2.95,0.975) 18(2.95,1.625) 19(2.95,2.275) 20(2.95,2.925)
  Top Overlay keep-out lines w0.2: -1.85,-3.3 1.85,-3.3
  silkscreen extent -3.5,-3.3 1.85,3.4, body extent -3.21,-3.25 3.21,3.25, height 1
SM_RADIAL_10BMM [mm] "Nichicon 10x10"
  rect 4x2.5 smd: 1(-4,0) 2(4,0)
  silkscreen extent -5.25,-5.25 5.25,5.25, body extent -5.25,-5.25 5.25,5.25, height 10.5
SM_RADIAL_H13 [mm] "12.5 x 13.5mm:  Panasonic H13"
  rect 5.7x2 smd: 1(-4.85,0) 2(4.85,0)
  silkscreen extent -6.85,-6.85 6.85,6.85, body extent -6.85,-6.85 6.85,6.85, height 14
SMA [mm] "Molded Diode, 2-Leads, Body 4.3x2.6mm, IPC Medium Density, based on OnSemi component dimensions and land pattern"
  rect 2x2 smd: 1(-2,0) 2(2,0)
  silkscreen extent -3.66,-1.57 2.79,1.57, body extent -2.6,-1.3 2.6,1.3, height 2.42
SMC [mil] "Molded Diode, 2-Leads, Body 6.9x5.8mm, IPC Medium Density, based on OnSemi component dimensions and land patterns"
  rect 110x150 smd: 1(-140.49,0) 2(140.49,0)
  silkscreen extent -221,-123 189,124, body extent -156,-116 156,116, height 91
SOD-123 [mm] "On Semi recommended land pattern"
  rect 0.915x1.22 smd: 1(-1.637,0) 2(1.637,0)
  silkscreen extent -2.74,-1.17 2.03,1.17, body extent -1.93,-0.9 1.93,0.9, height 1.35
SOD-323 [mm] "NXP recommended land pattern"
  rect 0.6x0.6 smd paste-0.05: 1(-1.1,0) 2(1.1,0)
  silkscreen extent -2.06,-0.86 1.53,0.86, body extent -1.3,-0.67 1.3,0.68, height 1.1
SOP-4 [mm] "Vishay Half Pitch Mini-Flat Package"
  rect 1.3x0.9 smd: 1(-3.15,0.635) 2(-3.15,-0.635) 3(3.15,-0.635) 4(3.15,0.635)
  silkscreen extent -2.2,-1.41 2.2,1.39, body extent -3.5,-1.4 3.5,1.4, height 2.12
SOT-323 [mm] "Diodes Inc recommended land pattern.  2016-02-24"
  rrect21% 0.6x0.47 smd: 1(-0.95,0.65) 2(-0.95,-0.65) 3(0.95,0)
  silkscreen extent -1.14,-1.22 0.77,1.22, body extent -1.13,-1.13 1.12,1.12, height 1.13
TO-220AB [mil] "Copied from Altium's version of TO3B"
  rrect25% 76x118.11 hole 50: 1(-100,0)
  oval 76x118.11 hole 50: 2(0,0) 3(100,0)
  silkscreen extent -221,-59 221,126, body extent -221,-59 221,126, height 765
TSW-102-07-G-S [mm] "Samtec 100mil, 1x2, 230 mil above insulator"
  rrect50% 1.65x1.65 hole 1.016: 1(-1.27,0)
  round 1.65 hole 1.016: 2(1.27,0)
  silkscreen extent -3.17,-1.27 2.54,1.27, body extent -2.54,-1.27 2.54,1.27, height 8.38
WEEE_Minimum [mil] "WEEElie bin"
  silkscreen extent -95,-172 99,104
Wurth_691236510002 [mm] "Terminal Block, 5.08mm, 2x1, R/A, TH"
  rrect50% 2.25x2.25 hole 1.5: 1(-2.54,0)
  round 2.25 hole 1.5: 2(2.54,0)
  body extent -5.68,-5.5 5.08,5.85, height 18

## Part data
C1 C4 C29: library part CMP-0006867-4, "CAP, CERM, 1 uF, 25 V, +/- 10%, X7R, 0603", Cap_Case=0603, Manufacturer=Kemet, Supplier Part Number 1=399-7376-1-ND, TempCo=X7R, Tolerance_%=10%, Value1=Unknown, Value2=25V, ValueDisplayed=1uF
C2: library part CMP-0007423-5, "CAP, CERM, 0.047 uF, 25 V, +/- 10%, X7R, 0603", Cap_Case=0603, Manufacturer=MuRata, Supplier Part Number 1=490-1522-1-ND, TempCo=X7R, Tolerance_%=10%, Value1=Unknown, Value2=25V, ValueDisplayed=0.047uF
C3 C9: library part CMP-0007730-2, "CAP, CERM, 1 uF, 50 V, +/- 10%, X7R, 0805", Cap_Case=0805, Manufacturer=Kemet, Supplier Part Number 1=399-7409-1-ND, TempCo=X7R, Tolerance_%=10%, Value1=Unknown, Value2=50V, ValueDisplayed=1uF
C5 C6: library part CMP-0011211-2, "CAP, AL, 330 uF, 50 V, +/- 20%, 0.12 ohm, AEC-Q200 Grade 2, SMD", Cap_Case=H13, Manufacturer=Panasonic, Supplier Part Number 1=PCE3475CT-ND, Tolerance_%=20%, Value1="0.12 ohm", Value2=50V, ValueDisplayed=330uF
C7 C8 C100 C101: library part CMP-0012603-3, "CAP, Polymer Hybrid, 82 uF, 63 V, +/- 20%, 30 ohm, 10x10 SMD", Manufacturer="United Chem-Con", Supplier Part Number 1=P15469CT-ND, Tolerance_%=20%, Value1="30 ohm", Value2=63V, ValueDisplayed=82uF
C10: library part CMP-0006861-4, "CAP, CERM, 0.1 uF, 50 V, +/- 10%, X7R, 0603", Cap_Case=0603, Manufacturer=Kemet, Supplier Part Number 1=399-5089-1-ND, TempCo=X7R, Tolerance_%=10%, Value1=Unknown, Value2=50V, ValueDisplayed=0.1uF
C11 C12 C13 C14 C15: library part CMP-0009259-2, "CAP, CERM, 10 uF, 50 V, +/- 10%, X7R, 1210", Cap_Case=1210, Manufacturer="Taiyo Yuden", Supplier Part Number 1=587-3167-1-ND, TempCo=X7R, Tolerance_%=10%, Value1=Unknown, Value2=50V, ValueDisplayed=10uF
C16 C17 C18 C19: library part CMP-0009084-1, "CAP, CERM, 2.2 uF, 100 V, +/- 10%, X7R, 1210", Cap_Case=1210, Manufacturer=Kemet, Supplier Part Number 1=399-5511-2-ND, TempCo=X7R, Tolerance_%=10%, Value1=Unknown, Value2=100V, ValueDisplayed=2.2uF
C20: library part CMP-0008999-2, "CAP, CERM, 0.15 uF, 100 V, +/- 10%, X7R, 1206", Cap_Case=0805, Manufacturer=MuRata, Supplier Part Number 1=490-3365-1-ND, TempCo=X7R, Tolerance_%=10%, Value1=Unknown, Value2=100V, ValueDisplayed=0.15uF
C21: library part CMP-0009358-2, "CAP, CERM, 2200 pF, 2000 V, +/- 10%, X7R, 1812", Cap_Case=1812, Manufacturer=TDK, Supplier Part Number 1=445-2389-1-ND, TempCo=X7R, Tolerance_%=10%, Value1=Unknown, Value2=2000V, ValueDisplayed=2200pF
C22 C33: library part CMP-0006832-5, "CAP, CERM, 0.1 uF, 25 V, +/- 10%, X7R, 0603", Cap_Case=0603, Manufacturer="Wurth Elektronik", Supplier Part Number 1=710-885012206071, TempCo=X7R, Tolerance_%=10%, Value1=Unknown, Value2=25V, ValueDisplayed=0.1uF
C23 C24 C28: library part CMP-0064933-4, "CAP, CERM, 1000 pF, 50 V,+/- 10%, X7R, 0603", Cap_Case=0603, Manufacturer="Wurth Elektronik", Supplier Part Number 1=732-8001-1-ND, TempCo=X7R, Tolerance_%=10%, Value1=Unknown, Value2=50V, ValueDisplayed=1000pF
C25: library part CMP-0006839-4, "CAP, CERM, 10 pF, 50 V, +/- 5%, C0G/NP0, 0603", Cap_Case=0603, Manufacturer=Kemet, Supplier Part Number 1=399-1049-1-ND, TempCo=C0G/NP0, Tolerance_%=5%, Value1=Unknown, Value2=50V, ValueDisplayed=10pF
C26: library part CMP-0006822-4, "CAP, CERM, 100 pF, 50 V, +/- 5%, C0G/NP0, 0603", Cap_Case=0603, Manufacturer="Wurth Elektronik", TempCo=C0G/NP0, Tolerance_%=5%, Value1=Unknown, Value2=50V, ValueDisplayed=100pF
C27: library part CMP-0750069-1, "CAP, CERM, 0.068 µF, 25 V,+/- 10%, X7R, 0603", Cap_Case=0603, Manufacturer="Wurth Elektronik", TempCo=X7R, Tolerance_%=10%, Value2=25V, ValueDisplayed=0.068µF
C30 C34 C35 C36 C37: library part CMP-0006854-4, "CAP, CERM, 0.01 uF, 50 V, +/- 10%, X7R, 0603", Cap_Case=0603, Manufacturer=Kemet, Supplier Part Number 1=399-1091-1-ND, TempCo=X7R, Tolerance_%=10%, Value1=Unknown, Value2=50V, ValueDisplayed=0.01uF
C31: library part CMP-0006939-4, "CAP, CERM, 47 pF, 50 V, +/- 5%, C0G/NP0, 0603", Cap_Case=0603, Manufacturer=Kemet, Supplier Part Number 1=399-1056-1-ND, TempCo=C0G/NP0, Tolerance_%=5%, Value1=Unknown, Value2=50V, ValueDisplayed=47pF
C32 C38: library part CMP-0750070-1, "CAP, CERM, 10 µF, 16 V,+/- 10%, X7R, 1206", Cap_Case=1206, Manufacturer="Wurth Elektronik", TempCo=X7R, Tolerance_%=10%, Value2=16V, ValueDisplayed=10µF
C39 C40: library part CMP-0009046-2, "CAP, CERM, 220 pF, 500 V, +/- 10%, X7R, 1206", Cap_Case=1206, Manufacturer=Vishay-Vitramon, Supplier Part Number 1=720-1023-1-ND, TempCo=X7R, Tolerance_%=10%, Value1=Unknown, Value2=500V, ValueDisplayed=220pF
C41: library part CMP-0009042-2, "CAP, CERM, 0.01 uF, 500 V, +/- 10%, X7R, 1206", Cap_Case=1206, Manufacturer=Vishay-Vitramon, Supplier Part Number 1=720-1021-1-ND, TempCo=X7R, Tolerance_%=10%, Value1=Unknown, Value2=500V, ValueDisplayed=0.01uF
C102: library part CMP-0006888-4, "CAP, CERM, 180 pF, 50 V, +/- 5%, C0G/NP0, 0603", Cap_Case=0603, Manufacturer=Kemet, Supplier Part Number 1=399-1064-1-ND, TempCo=C0G/NP0, Tolerance_%=5%, Value1=Unknown, Value2=50V, ValueDisplayed=180pF
D1: library part CMP-0029032-2, "Diode, Switching, 100 V, 0.2 A, SOD-123", Manufacturer="ON Semiconductor", Value1=0.2A, Value2=1V
D2: library part CMP-0076962-2, "Diode, Ultrafast, 400 V, 3 A, SMC", Manufacturer="ON Semiconductor", Value1=3A, Value2=1.25V
D3: library part CMP-0005832-4, "Diode, Zener, 13 V, 200 mW, SOD-323", Manufacturer="Diodes Inc.", Power_W=200mW, Value1=0.2W
D4 D10: library part CMP-0077080-4, "Diode, Hyperafast, 300 V, 2x 15 A, TH", Manufacturer=Vishay, Value1=30A, Value2=1.2V
D5: library part CMP-0076993-2, "Diode, Fast Rectifier, 200 V, 0.8 A, SOD-123", Manufacturer=Rohm, Value1=0.8A, Value2=0.95V
D6 D7 D8 D9 D100: library part CMP-0029045-2, "Diode, Switching, 100 V, 0.2 A, SOD-323", Manufacturer="Micro Commercial Components", Value1=0.2A, Value2=1V
D11 D12: library part CMP-0029029-4, "Diode, Ultrafast, 300 V, 30 A, DDPAK", Manufacturer=STMicroelectronics, Value1=30A, Value2=1V
D13: library part CMP-0028371-2, "Diode, Schottky, 100 V, 1 A, SMA", Manufacturer="Diodes Inc.", Value1=1A, Value2=0.79V
D14: library part CMP-0029022-2, "Diode, Superfast Rectifier, 100 V, 1 A, SMA", Manufacturer="Diodes Inc.", Value1=1A, Value2=0.92V
H1 H2: library part CMP-0084930-1, "Heat Sink TO-220, TO-218 Aluminum  Board Level, Vertical", Digikey Part Number=345-1027-ND, Manufacturer=Wakefield-Vette, Mating Package=TO-220/TO-218, Mouser Part Number=567-634-20ABP, Operating Temperature Range=to
J1 J2: library part CMP-0079044-1, "Terminal Block, 5.08mm, 2x1, R/A, TH", Color=Green, Current_A=20A, Manufacturer="Wurth Elektronik", Supplier Part Number 1=732-10995-ND, Voltage_V=300V
J3 J4: library part CMP-0075405-3, "Header, 100mil, 2x1, Gold, TH", Color=Black, Current_A=6.3A, Manufacturer=Samtec, Supplier Part Number 1=SAM1029-02-ND, Voltage_V=550V
L1: library part CMP-0079793-1, "Inductor, Shielded, 4.7 µH, 10 A, 0.0155 ohm, AEC-Q200 Grade 1, SMD", Manufacturer="Pulse Engineering", Supplier Part Number 1=553-3001-1-ND, Value1="0.0155 ohm", Value2=10A, ValueDisplayed=4.7µH
L2: library part CMP-0095492-1, "Shielded Power Inductors 33uH 10% 2.82mOhm 28A", Manufacturer=Coilcraft, Operating Temperature Range=to, Self Resonant Frequency=10MHz, Test Frequency=500kHz, Tolerance_%=10%
Logo1: library part CMP-0074769-1
Logo2: library part CMP-0074847-1, "FCC_disclaimer"
Logo3 Logo4 Logo5: library part CMP-0074837-2, "IEC 61010-1 Hot Surface Warning", Manufacturer="Texas Instruments"
Q1: library part CMP-0000481-4, "Transistor, NPN, 50 V, 2 A, AEC-Q101, DPAK", Manufacturer="ON Semiconductor", Value1="2 A", Value2=360
Q3: library part CMP-0000056-3, "MOSFET, P-CH, -150 V, -3 A, QFN-8", Alternate Manufacturer=None, Manufacturer="Fairchild Semiconductor", Value2="6.2 nC"
Q4 Q6: library part CMP-0000958-3, "MOSFET, N-CH, 100 V, 17 A, DNK0008A (VSON-CLIP-8)", Alternate Manufacturer=None, Manufacturer="Texas Instruments", Supplier Part Number 1=296-37478-6-ND, Value2="48 nC"
Q5 Q8: library part CMP-0000776-1, "MOSFET, N-CH, 60 V, 0.115 A, SOT-323", Alternate Manufacturer=None, Manufacturer="Diodes Inc.", Supplier Part Number 1=2N7002W-FDICT-ND, Value1=7
R1: library part CMP-0020572-3, "RES, 5.1 k, 5%, 0.125 W, AEC-Q200 Grade 0, 0805", Manufacturer=Vishay-Dale, Power_W=125mW, Supplier Part Number 1=541-5.1KACT-ND, TempCo="200 ppm/C", Tolerance_%=5%, Value2=0.125W, Value_Code=5k10, ValueDisplayed=5.1k
R2 R27 R28: library part CMP-0022126-4, "RES, 1.50 k, 1%, 0.1 W, AEC-Q200 Grade 0, 0603", Manufacturer=Vishay-Dale, Power_W=100mW, Supplier Part Number 1=541-1.50KHCT-ND, TempCo="100 ppm/C", Tolerance_%=1%, Value2=0.1W, Value_Code=1k50, ValueDisplayed=1.50k
R3: library part CMP-0016551-2, "RES, 0.005, 1%, 0.5 W, 2010", Manufacturer=Vishay-Dale, Power_W=500mW, Supplier Part Number 1=WSLE-.005CT-ND, TempCo="110 ppm/C", Tolerance_%=1%, Value2=0.5W, Value_Code=5L000, ValueDisplayed=0.005
R4 R26: library part CMP-0025697-4, "RES, 0, 5%, 0.1 W, AEC-Q200 Grade 0, 0603", Manufacturer=Vishay-Dale, Power_W=100mW, Supplier Part Number 1=541-0.0GCT-ND, TempCo="200 ppm/C", Tolerance_%=5%, Value2=0.1W, Value_Code=0000, ValueDisplayed=0
R5 R6: library part CMP-0022532-4, "RES, 60.4 k, 1%, 0.1 W, AEC-Q200 Grade 0, 0603", Manufacturer=Vishay-Dale, Power_W=100mW, Supplier Part Number 1=541-60.4KHCT-ND, TempCo="100 ppm/C", Tolerance_%=1%, Value2=0.1W, Value_Code=60k4, ValueDisplayed=60.4k
R7: library part CMP-0022324-4, "RES, 30.1 k, 1%, 0.1 W, AEC-Q200 Grade 0, 0603", Manufacturer=Vishay-Dale, Power_W=100mW, Supplier Part Number 1=541-30.1KHCT-ND, TempCo="100 ppm/C", Tolerance_%=1%, Value2=0.1W, Value_Code=30k1, ValueDisplayed=30.1k
R8: library part CMP-0022458-4, "RES, 4.99 k, 1%, 0.1 W, AEC-Q200 Grade 0, 0603", Manufacturer=Vishay-Dale, Power_W=100mW, Supplier Part Number 1=541-4.99KHCT-ND, TempCo="100 ppm/C", Tolerance_%=1%, Value2=0.1W, Value_Code=4k99, ValueDisplayed=4.99k
R9 R15 R18 R31 R33: library part CMP-0021998-4, "RES, 10.0 k, 1%, 0.1 W, AEC-Q200 Grade 0, 0603", Manufacturer=Vishay-Dale, Power_W=100mW, Supplier Part Number 1=541-10.0KHCT-ND, TempCo="100 ppm/C", Tolerance_%=1%, Value2=0.1W, Value_Code=10k0, ValueDisplayed=10.0k
R10 R22: library part CMP-0022268-4, "RES, 2.00 k, 1%, 0.1 W, AEC-Q200 Grade 0, 0603", Manufacturer=Vishay-Dale, Power_W=100mW, Supplier Part Number 1=541-2.00KHCT-ND, TempCo="100 ppm/C", Tolerance_%=1%, Value2=0.1W, Value_Code=2k00, ValueDisplayed=2.00k
R11: library part CMP-0022187-4, "RES, 1.50, 1%, 0.1 W, AEC-Q200 Grade 0, 0603", Manufacturer=Vishay-Dale, Power_W=100mW, Supplier Part Number 1=541-1.50HHCT-ND, TempCo="100 ppm/C", Tolerance_%=1%, Value2=0.1W, Value_Code=1R50, ValueDisplayed=1.50
R12: library part CMP-0022599-4, "RES, 7.15 k, 1%, 0.1 W, AEC-Q200 Grade 0, 0603", Manufacturer=Vishay-Dale, Power_W=100mW, Supplier Part Number 1=541-7.15KHCT-ND, TempCo="100 ppm/C", Tolerance_%=1%, Value2=0.1W, Value_Code=7k15, ValueDisplayed=7.15k
R13: library part CMP-0022066-4, "RES, 15.0 k, 1%, 0.1 W, AEC-Q200 Grade 0, 0603", Manufacturer=Vishay-Dale, Power_W=100mW, Supplier Part Number 1=541-15.0KHCT-ND, TempCo="100 ppm/C", Tolerance_%=1%, Value2=0.1W, Value_Code=15k0, ValueDisplayed=15.0k
R14: library part CMP-0022510-4, "RES, 5.23 k, 1%, 0.1 W, AEC-Q200 Grade 0, 0603", Manufacturer=Vishay-Dale, Power_W=100mW, Supplier Part Number 1=541-5.23KHCT-ND, TempCo="100 ppm/C", Tolerance_%=1%, Value2=0.1W, Value_Code=5k23, ValueDisplayed=5.23k
R16: library part CMP-0022001-4, "RES, 10.7 k, 1%, 0.1 W, AEC-Q200 Grade 0, 0603", Manufacturer=Vishay-Dale, Power_W=100mW, Supplier Part Number 1=541-10.7KHCT-ND, TempCo="100 ppm/C", Tolerance_%=1%, Value2=0.1W, Value_Code=10k7, ValueDisplayed=10.7k
R17: library part CMP-0022036-4, "RES, 130 k, 1%, 0.1 W, AEC-Q200 Grade 0, 0603", Manufacturer=Vishay-Dale, Power_W=100mW, Supplier Part Number 1=541-130KHCT-ND, TempCo="100 ppm/C", Tolerance_%=1%, Value2=0.1W, Value_Code=130k
R19 R29: library part CMP-0021990-4, "RES, 100 k, 1%, 0.1 W, AEC-Q200 Grade 0, 0603", Manufacturer=Vishay-Dale, Power_W=100mW, Supplier Part Number 1=541-100KHCT-ND, TempCo="100 ppm/C", Tolerance_%=1%, Value2=0.1W, Value_Code=100k
R20 R35: library part CMP-0022008-4, "RES, 110 k, 1%, 0.1 W, AEC-Q200 Grade 0, 0603", Manufacturer=Vishay-Dale, Power_W=100mW, Supplier Part Number 1=541-110KHCT-ND, TempCo="100 ppm/C", Tolerance_%=1%, Value2=0.1W, Value_Code=110k
R21: library part CMP-0022408-4, "RES, 402 k, 1%, 0.1 W, AEC-Q200 Grade 0, 0603", Manufacturer=Vishay-Dale, Power_W=100mW, Supplier Part Number 1=541-402KHCT-ND, TempCo="100 ppm/C", Tolerance_%=1%, Value2=0.1W, Value_Code=402k
R23 R25: library part CMP-0022544-4, "RES, 64.9 k, 1%, 0.1 W, AEC-Q200 Grade 0, 0603", Manufacturer=Vishay-Dale, Power_W=100mW, Supplier Part Number 1=541-64.9KHCT-ND, TempCo="100 ppm/C", Tolerance_%=1%, Value2=0.1W, Value_Code=64k9, ValueDisplayed=64.9k
R24: library part CMP-0025777-4, "RES, 2.2, 5%, 0.1 W, AEC-Q200 Grade 0, 0603", Manufacturer=Vishay-Dale, Power_W=100mW, Supplier Part Number 1=541-2.2GCT-ND, TempCo="200 ppm/C", Tolerance_%=5%, Value2=0.1W, Value_Code=2R20, ValueDisplayed=2.2
R30: library part CMP-0022531-5, "RES, 604, 1%, 0.1 W, AEC-Q200 Grade 0, 0603", Manufacturer=Vishay-Dale, Power_W=100mW, Supplier Part Number 1=541-604HCT-ND, TempCo="100 ppm/C", Tolerance_%=1%, Value2=0.1W, Value_Code=604R, ValueDisplayed=604
R32: library part CMP-0022114-4, "RES, 1.13 k, 1%, 0.1 W, AEC-Q200 Grade 0, 0603", Manufacturer=Vishay-Dale, Power_W=100mW, Supplier Part Number 1=541-1.13KHCT-ND, TempCo="100 ppm/C", Tolerance_%=1%, Value2=0.1W, Value_Code=1k13, ValueDisplayed=1.13k
R34: library part CMP-0022584-5, "RES, 732, 1%, 0.1 W, AEC-Q200 Grade 0, 0603", Manufacturer=Vishay-Dale, Power_W=100mW, Supplier Part Number 1=541-732HCT-ND, TempCo="100 ppm/C", Tolerance_%=1%, Value2=0.1W, Value_Code=732R, ValueDisplayed=732
R36: library part CMP-0022098-4, "RES, 18.7 k, 1%, 0.1 W, AEC-Q200 Grade 0, 0603", Manufacturer=Vishay-Dale, Power_W=100mW, Supplier Part Number 1=541-18.7KHCT-ND, TempCo="100 ppm/C", Tolerance_%=1%, Value2=0.1W, Value_Code=18k7, ValueDisplayed=18.7k
R37 R38 R39 R40: library part CMP-0015884-3, "RES, 150, 5%, 1 W, AEC-Q200 Grade 0, 2512", Manufacturer=Vishay-Dale, Power_W=1W, Supplier Part Number 1=541-150XCT-ND, TempCo="200 ppm/C", Tolerance_%=5%, Value_Code=150R, ValueDisplayed=150
R41 R42: library part CMP-0015953-3, "RES, 39 k, 5%, 1 W, AEC-Q200 Grade 0, 2512", Manufacturer=Vishay-Dale, Power_W=1W, Supplier Part Number 1=541-39KXCT-ND, TempCo="200 ppm/C", Tolerance_%=5%, Value_Code=39k0, ValueDisplayed=39k
T1: library part CMP-0094349-1, "Flyback Transformer, 5.5mOhm PRI, 1:0.25:1.25, 250kHz, 1500VAC, 27.1x26.42x14.5mm", Frequency_Fixed=250kHz, Manufacturer=Pulse, Operating Temperature Range="-40°C to +125°C", Voltage_Isolation_Vrms=1.5kV
T2: library part CMP-0030386-2, "SMT Current Sense Tranformer", Manufacturer="Pulse Engineering", Supplier Part Number 1=553-1529-1-ND
U1: library part CMP-0031995-1, "Advanced Active Clamp PWM Controller with Current-Mode Control, -40 to +125 degC, 20-pin TSSOP (PW), Green (RoHS & no Sb/Br)", Frequency(Max)(kHz)=1000, Manufacturer="Texas Instruments", Rating=Catalog
U2: library part CMP-0091995-1, "General Purpose Amplifier 2 Circuit Rail-to-Rail 8-WSON (2x2)", Digikey Part Number=296-OPA2170AIDSGRCT-ND, Input Bias Current=0.000008uA, Input Offset Voltage=0.25mV, Manufacturer="Texas Instruments", Max Dual Supply Voltage=18V, Max Supply Voltage=36V, Min Dual Supply Voltage=1.35V, Min Supply Voltage=2.7V, Mouser Part Number=595-OPA2170AIDSGR, Nominal Supply Current=110uA, Operating Temperature Range="-40°C to +125°C", Output Current Per Channel=-20mA, Voltage Gain=130dB
U3: library part CMP-0066949-1, "4A/4A Single Channel High-Speed Low-side Gate Driver, DBV0005A (SOT-23-5)", Alternate Manufacturer="Texas Instruments", Alternate PartNumber=UCC27519DBVT
U4: library part CMP-0032746-2, "Precision Micropower Shunt Voltage Reference, 1% accuracy, 5 V, 15 ppm / degC, 15 mA, -40 to 85 degC, 5-pin SC70 (DCK), Green (RoHS & no Sb/Br)", Manufacturer="Texas Instruments", Rating=Catalog, Temp Coeff(Max)(ppm/ degree C)=150, Temp Coeff(Typ)(ppm/ degree C)=15
U5: library part CMP-0006166-3, "Optocoupler, 3.75 kV, 80-160% CTR, SMT", Manufacturer=Vishay-Semiconductor, Supplier Part Number 1=TCMT1107CT-ND, Voltage_Isolation_Vrms=3.75kV
U6: library part CMP-0035939-4, "60V, 5uA Iq, 100mA Low-Dropout (LDO) Voltage Regulator With Enable and Power Good, DGN0008C (VSSOP-8)", Alternate Manufacturer="Texas Instruments", Alternate PartNumber=TPS7A1601DGNT, Power Good=TRUE, Rating=Catalog

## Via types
v1: diameter 40, hole 18, Top Layer to Bottom Layer, 148 vias
v2: diameter 30, hole 12, Top Layer to Bottom Layer, 51 vias
v3: diameter 19.68, hole 7.87, Top Layer to Bottom Layer, tented both sides, 4 vias
v4: diameter 19.68, hole 7.87, Top Layer to Bottom Layer, 4 vias

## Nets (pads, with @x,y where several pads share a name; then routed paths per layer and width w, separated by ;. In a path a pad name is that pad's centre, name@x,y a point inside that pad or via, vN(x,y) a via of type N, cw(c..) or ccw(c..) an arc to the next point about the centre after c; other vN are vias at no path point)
5VREF: C36.2 R19.2 R22.2 R35.1 U4.3 | length 947.3
  Top Layer w15: v1(670,480) 671.22,481.22 733.78,481.22 R22.2@734.65,482.09 ; U4.3@734.29,420.59 734.65,420.94 R22.2@734.65,482.09 ; R22.2@735,482.44 R22.2@734.65,482.09 ; v1(890,480) 892.5,482.5 969.94,482.5 C36.2@972.44,485 R35.1@972.44,430 ; v1(1205,265) 1206.28,266.28 1206.28,318.72 R19.2@1207.56,320
  Bottom Layer w15: v1(670,480) v1(890,480) 990,480 v1(1205,265)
